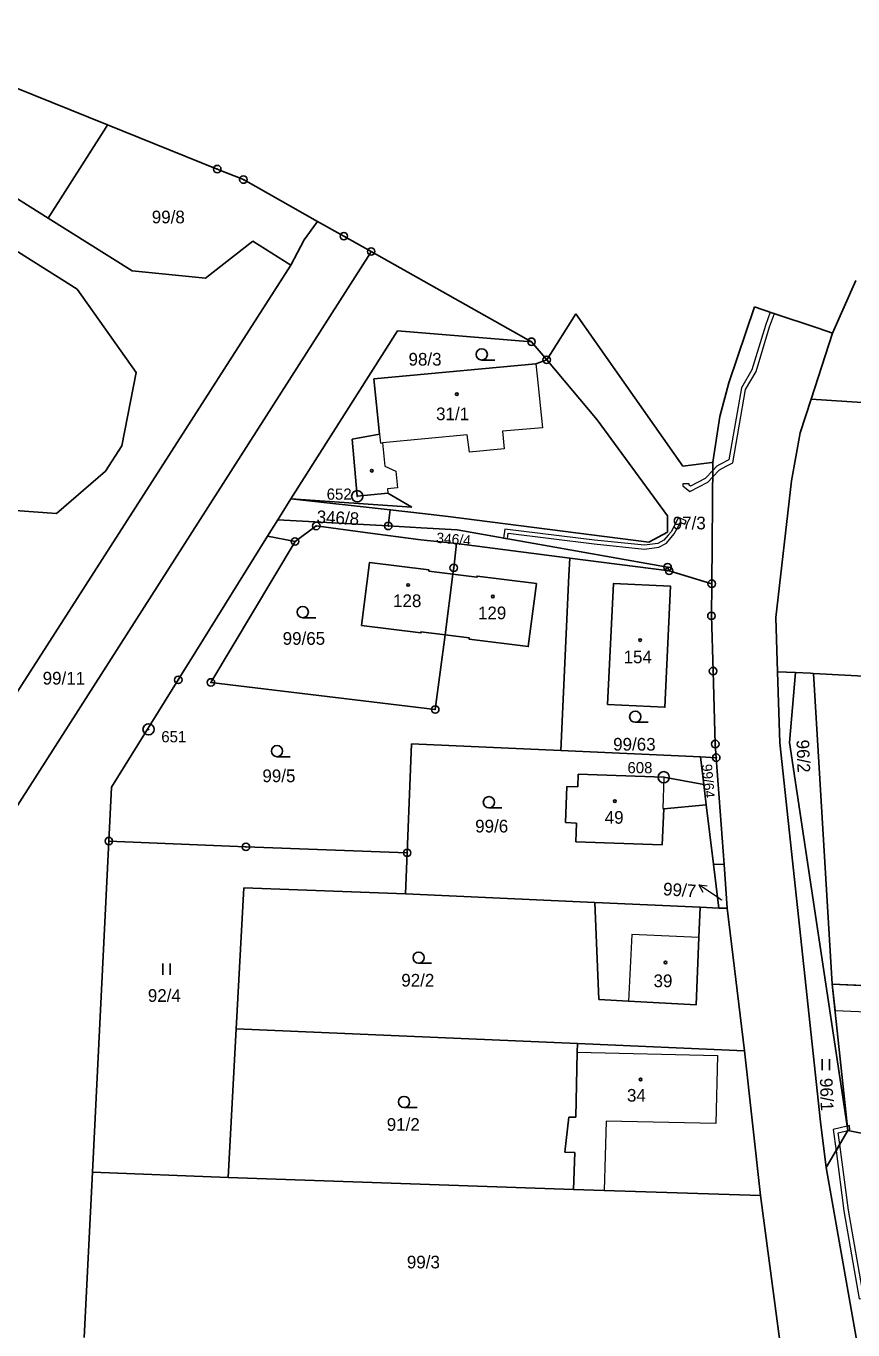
# Model space of a CAD drawing. Extents: x -645290 to -643454, y -1064771 to -1062356.
# Drawn here: x -644687.8 to -644577, y -1063528 to -1063353.2 of the extents above; entities that cross this region are included whole.
import ezdxf
from ezdxf.enums import TextEntityAlignment as Align

# ---------------------------------------------------------------- set-up
doc = ezdxf.new("R2010")
doc.units = 0
doc.header["$LTSCALE"] = 0.68
for name, color, linetype, lineweight in [('1', 7, 'Continuous', 25), ('13', 7, 'Continuous', 13), ('3', 7, 'Continuous', 25), ('4', 7, 'Continuous', 13), ('5', 7, 'Continuous', 25), ('7', 7, 'Continuous', 13), ('8', 7, 'Continuous', 25)]:
    doc.layers.add(name, color=color, linetype=linetype, lineweight=lineweight)
doc.layers.add('2', color=7, linetype='Continuous')

msp = doc.modelspace()

# ---------------------------------------------------------------- linework, layer by layer
at = {"layer": '1'}
for p, q in [((-644737.26, -1063353.21), (-644680.96, -1063388.46)), ((-644684.84, -1063378.96), (-644720.02, -1063356.92)), ((-644696.48, -1063358.55), (-644676.89, -1063366.45)), ((-644684.84, -1063378.96), (-644677.09, -1063366.77)), ((-644677.09, -1063366.77), (-644676.89, -1063366.45)), ((-644676.89, -1063366.45), (-644662.2, -1063372.38)), ((-644673.59, -1063386.01), (-644684.84, -1063378.96)), ((-644648.9, -1063379.59), (-644650.56, -1063381.87)), ((-644648.9, -1063379.59), (-644648.76, -1063379.39)), ((-644648.76, -1063379.39), (-644645.24, -1063381.37)), ((-644657.45, -1063382.05), (-644663.77, -1063387.01)), ((-644652.35, -1063385.28), (-644657.45, -1063382.05)), ((-644650.56, -1063381.87), (-644652.35, -1063385.28)), ((-644645.24, -1063381.37), (-644641.58, -1063383.43)), ((-644641.68, -1063383.59), (-644696.8, -1063469.92)), ((-644641.68, -1063383.59), (-644641.58, -1063383.43)), ((-644641.58, -1063383.43), (-644620.1, -1063395.53)), ((-644693.66, -1063449.74), (-644652.35, -1063385.28)), ((-644663.77, -1063387.01), (-644673.59, -1063386.01)), ((-644579.76, -1063394.36), (-644576.65, -1063387.33)), ((-644680.96, -1063388.46), (-644673.07, -1063399.66)), ((-644593.65, -1063401.05), (-644590.22, -1063390.86)), ((-644590.22, -1063390.86), (-644587.75, -1063391.69)), ((-644618.06, -1063397.95), (-644614.16, -1063391.77)), ((-644614.16, -1063391.77), (-644606.24, -1063403.04)), ((-644587.75, -1063391.69), (-644581.68, -1063393.72)), ((-644652.34, -1063416.6), (-644638.07, -1063394.05)), ((-644638.07, -1063394.05), (-644620.1, -1063395.53)), ((-644582.64, -1063403.23), (-644579.76, -1063394.36)), ((-644581.68, -1063393.72), (-644579.76, -1063394.36)), ((-644620.1, -1063395.53), (-644618.06, -1063397.95)), ((-644619.51, -1063398.51), (-644641.21, -1063400.48)), ((-644618.06, -1063397.95), (-644619.51, -1063398.51)), ((-644673.07, -1063399.66), (-644675, -1063409.48)), ((-644641.21, -1063400.48), (-644640.45, -1063407.93)), ((-644593.65, -1063401.05), (-644594.86, -1063405.54)), ((-644599.81, -1063412.19), (-644606.24, -1063403.04)), ((-644584.11, -1063407.75), (-644582.64, -1063403.23)), ((-644534.36, -1063406.42), (-644582.64, -1063403.23)), ((-644595.81, -1063411.69), (-644594.86, -1063405.54)), ((-644640.45, -1063407.93), (-644644.14, -1063408.59)), ((-644644.14, -1063408.59), (-644643.45, -1063416.24)), ((-644585.27, -1063414.18), (-644584.11, -1063407.75)), ((-644675, -1063409.48), (-644677.18, -1063412.9)), ((-644599.81, -1063412.19), (-644595.95, -1063411.71)), ((-644595.81, -1063411.69), (-644595.95, -1063427.97)), ((-644595.81, -1063411.69), (-644595.95, -1063411.71)), ((-644677.18, -1063412.9), (-644683.76, -1063418.54)), ((-644585.27, -1063414.18), (-644587.35, -1063432.48)), ((-644643.45, -1063416.24), (-644639.34, -1063415.83)), ((-644639.34, -1063415.83), (-644636.15, -1063417.71)), ((-644683.76, -1063418.54), (-644694.51, -1063417.77)), ((-644654.08, -1063419.4), (-644652.34, -1063416.6)), ((-644636.15, -1063417.71), (-644652.34, -1063416.6)), ((-644639.01, -1063418.08), (-644652.34, -1063416.6)), ((-644655.46, -1063421.61), (-644654.08, -1063419.4)), ((-644639.29, -1063420.22), (-644654.08, -1063419.4)), ((-644639.01, -1063418.08), (-644639.29, -1063420.22)), ((-644634.72, -1063418.55), (-644639.01, -1063418.08)), ((-644631.25, -1063418.96), (-644634.72, -1063418.55)), ((-644604.39, -1063422.39), (-644631.25, -1063418.96)), ((-644601.87, -1063418.87), (-644601.88, -1063421.06)), ((-644651.78, -1063422.31), (-644648.93, -1063420.23)), ((-644648.93, -1063420.23), (-644642.39, -1063421.09)), ((-644642.39, -1063421.09), (-644634.94, -1063422.08)), ((-644634.87, -1063420.47), (-644639.29, -1063420.22)), ((-644630.04, -1063420.74), (-644634.87, -1063420.47)), ((-644601.86, -1063425.75), (-644630.04, -1063420.74)), ((-644601.88, -1063421.06), (-644604.39, -1063422.39)), ((-644665.05, -1063437.05), (-644655.46, -1063421.61)), ((-644651.78, -1063422.31), (-644663.05, -1063441.2)), ((-644651.78, -1063422.31), (-644655.46, -1063421.61)), ((-644634.94, -1063422.08), (-644630.14, -1063422.56)), ((-644630.52, -1063425.84), (-644630.14, -1063422.56)), ((-644630.14, -1063422.56), (-644614.97, -1063424.54)), ((-644615.08, -1063426.87), (-644614.97, -1063424.54)), ((-644614.97, -1063424.54), (-644601.65, -1063426.24)), ((-644601.65, -1063426.24), (-644601.86, -1063425.75)), ((-644595.95, -1063427.97), (-644601.65, -1063426.24)), ((-644631.67, -1063434.83), (-644630.62, -1063426.69)), ((-644616.18, -1063450.33), (-644615.08, -1063426.87)), ((-644595.95, -1063427.97), (-644595.99, -1063432.28)), ((-644595.99, -1063432.28), (-644595.77, -1063439.68)), ((-644587.35, -1063432.48), (-644587.12, -1063439.78)), ((-644667.42, -1063440.86), (-644665.05, -1063437.05)), ((-644595.77, -1063439.68), (-644595.47, -1063449.46)), ((-644584.72, -1063439.88), (-644587.12, -1063439.78)), ((-644587.12, -1063439.78), (-644586.83, -1063449.3)), ((-644584.72, -1063439.88), (-644585.51, -1063449.26)), ((-644582.7, -1063439.97), (-644584.72, -1063439.88)), ((-644582.31, -1063439.99), (-644582.7, -1063439.97)), ((-644582.31, -1063439.99), (-644579.79, -1063481.67)), ((-644500.64, -1063444.4), (-644582.31, -1063439.99)), ((-644676.36, -1063455.23), (-644667.42, -1063440.86)), ((-644585.51, -1063449.26), (-644577.69, -1063501.25)), ((-644636.17, -1063449.42), (-644636.75, -1063464.05)), ((-644616.18, -1063450.33), (-644636.17, -1063449.42)), ((-644597.46, -1063451.19), (-644616.18, -1063450.33)), ((-644595.47, -1063449.46), (-644595.34, -1063451.29)), ((-644586.83, -1063449.3), (-644581.37, -1063500.1)), ((-644597.46, -1063451.19), (-644595.34, -1063451.29)), ((-644597.01, -1063454.88), (-644597.46, -1063451.19)), ((-644595.34, -1063451.29), (-644594.29, -1063465.62)), ((-644613.84, -1063453.49), (-644613.9, -1063455.19)), ((-644602.38, -1063453.91), (-644613.84, -1063453.49)), ((-644597.01, -1063454.88), (-644602.38, -1063453.91)), ((-644676.72, -1063462.47), (-644676.36, -1063455.23)), ((-644615.37, -1063455.14), (-644615.55, -1063460)), ((-644613.9, -1063455.19), (-644615.37, -1063455.14)), ((-644596.67, -1063457.63), (-644597.01, -1063454.88)), ((-644602.36, -1063458.13), (-644596.67, -1063457.63)), ((-644595.7, -1063465.56), (-644596.67, -1063457.63)), ((-644602.57, -1063462.99), (-644602.36, -1063458.13)), ((-644615.55, -1063460), (-644614.05, -1063460.05)), ((-644614.05, -1063460.05), (-644614.14, -1063462.56)), ((-644678.93, -1063506.84), (-644676.72, -1063462.47)), ((-644658.36, -1063463.25), (-644676.72, -1063462.47)), ((-644636.75, -1063464.05), (-644658.36, -1063463.25)), ((-644614.14, -1063462.56), (-644602.57, -1063462.99)), ((-644636.97, -1063469.54), (-644636.75, -1063464.05)), ((-644594.29, -1063465.62), (-644595.7, -1063465.56)), ((-644594.98, -1063471.46), (-644595.7, -1063465.56)), ((-644594.29, -1063465.62), (-644593.86, -1063471.46)), ((-644658.65, -1063468.72), (-644659.65, -1063487.63)), ((-644636.97, -1063469.54), (-644658.65, -1063468.72)), ((-644611.61, -1063470.7), (-644636.97, -1063469.54)), ((-644611.61, -1063470.7), (-644611.07, -1063483.72)), ((-644597.49, -1063471.35), (-644611.61, -1063470.7)), ((-644597.66, -1063475.39), (-644597.49, -1063471.35)), ((-644594.98, -1063471.46), (-644597.49, -1063471.35)), ((-644593.86, -1063471.46), (-644594.98, -1063471.46)), ((-644593.86, -1063471.46), (-644591.55, -1063490.59)), ((-644598.03, -1063484.42), (-644597.66, -1063475.39)), ((-644579.79, -1063481.67), (-644536.58, -1063483.49)), ((-644579.79, -1063481.67), (-644577.69, -1063501.25)), ((-644611.07, -1063483.72), (-644607.08, -1063483.93)), ((-644607.08, -1063483.93), (-644598.03, -1063484.42)), ((-644613.96, -1063490.75), (-644614.17, -1063499.5)), ((-644613.93, -1063489.61), (-644613.96, -1063490.75)), ((-644591.55, -1063490.59), (-644613.93, -1063489.61)), ((-644591.55, -1063490.59), (-644589.39, -1063509.99)), ((-644615.09, -1063499.48), (-644615.64, -1063504.18)), ((-644614.17, -1063499.5), (-644615.09, -1063499.48)), ((-644581.37, -1063500.1), (-644580.6, -1063506.24)), ((-644577.69, -1063501.25), (-644580.6, -1063506.24)), ((-644577.69, -1063501.25), (-644539.22, -1063509.16)), ((-644615.64, -1063504.18), (-644614.31, -1063504.23)), ((-644614.31, -1063504.23), (-644614.48, -1063509.16)), ((-644680.03, -1063529.01), (-644678.93, -1063506.84)), ((-644660.73, -1063507.57), (-644678.93, -1063506.84)), ((-644580.6, -1063506.24), (-644576.45, -1063529.78)), ((-644614.48, -1063509.16), (-644660.73, -1063507.57)), ((-644610.34, -1063509.3), (-644614.48, -1063509.16)), ((-644589.39, -1063509.99), (-644610.34, -1063509.3)), ((-644589.39, -1063509.99), (-644586.6, -1063531.21))]:
    msp.add_line(p, q, dxfattribs=at)
for points in [[(-644662.2, -1063372.38), (-644658.7, -1063373.79), (-644648.76, -1063379.39)], [(-644618.06, -1063397.95), (-644611.28, -1063406.01), (-644601.87, -1063418.87)], [(-644642.86, -1063433.55), (-644641.78, -1063425.11), (-644633.84, -1063426.12), (-644633.85, -1063426.27), (-644630.62, -1063426.69), (-644630.52, -1063425.84)], [(-644630.62, -1063426.69), (-644627.4, -1063427.1), (-644627.38, -1063426.95), (-644619.43, -1063427.96), (-644620.54, -1063436.4), (-644628.45, -1063435.39), (-644628.43, -1063435.24), (-644631.67, -1063434.83)], [(-644631.67, -1063434.83), (-644634.91, -1063434.42), (-644634.92, -1063434.56), (-644642.86, -1063433.55)], [(-644663.05, -1063441.2), (-644632.99, -1063444.83), (-644631.67, -1063434.83)], [(-644613.93, -1063489.61), (-644659.65, -1063487.63), (-644660.73, -1063507.57)]]:
    msp.add_lwpolyline(points, dxfattribs=at)
msp.add_lwpolyline([(-644609.91, -1063444.16), (-644602.23, -1063444.53), (-644601.46, -1063428.31), (-644609.1, -1063427.93)], close=True, dxfattribs=at)
at = {"layer": '13'}
for points in [[(-644598.87, -1063415.59), (-644596.45, -1063414.34), (-644595.83, -1063413.68), (-644594.9, -1063412.68), (-644594.03, -1063412.22), (-644593.13, -1063411.74), (-644591.4, -1063401.92), (-644590.01, -1063399.54), (-644588.19, -1063393.54), (-644587.54, -1063391.76), (-644587.75, -1063391.69), (-644588.11, -1063391.57), (-644588.76, -1063393.35), (-644590.57, -1063399.3), (-644591.98, -1063401.71), (-644593.67, -1063411.34), (-644594.85, -1063411.98), (-644595.27, -1063412.2), (-644595.82, -1063412.79), (-644596.81, -1063413.86), (-644598.81, -1063414.88), (-644598.95, -1063414.77), (-644598.96, -1063414.56), (-644599.84, -1063414.59), (-644599.83, -1063414.86)], [(-644623.85, -1063421.84), (-644623.33, -1063421.93), (-644623.21, -1063421.21), (-644611.7, -1063422.63), (-644604.96, -1063423.32), (-644603.02, -1063423.05), (-644602.01, -1063422.53), (-644601.59, -1063422.03), (-644600.98, -1063421.28), (-644600.14, -1063419.77), (-644599.57, -1063420), (-644599.38, -1063419.53), (-644600.42, -1063419.11), (-644601.4, -1063421), (-644601.77, -1063421.44), (-644602.35, -1063422.15), (-644603.16, -1063422.57), (-644604.95, -1063422.82), (-644611.64, -1063422.13), (-644623.65, -1063420.65)], [(-644536.58, -1063483.49), (-644579.79, -1063481.67), (-644579.41, -1063485.19), (-644536.15, -1063487.01)], [(-644579.29, -1063503.99), (-644578.8, -1063503.15), (-644579, -1063501.6), (-644577.69, -1063501.25), (-644577.75, -1063500.67), (-644577.78, -1063500.67), (-644579.66, -1063501.12)], [(-644577.75, -1063500.67), (-644577.69, -1063501.25), (-644577.44, -1063501.18), (-644577.48, -1063500.6)], [(-644578.8, -1063503.15), (-644579.29, -1063503.99), (-644578.24, -1063512.03), (-644576.17, -1063523.83), (-644575.34, -1063523.8), (-644572.63, -1063523.71), (-644572.59, -1063523.88), (-644573.02, -1063523.99), (-644572.93, -1063524.37), (-644572.5, -1063524.26), (-644572.2, -1063525.52), (-644573.09, -1063525.56), (-644573.07, -1063526.16), (-644571.44, -1063526.09), (-644572.16, -1063523.09), (-644575.39, -1063523.2), (-644575.67, -1063523.21), (-644577.64, -1063511.94)]]:
    msp.add_lwpolyline(points, close=True, dxfattribs=at)
at = {"layer": '3'}
for p, q in [((-644626.763, -1063397.98), (-644625.013, -1063397.98)), ((-644650.743, -1063432.53), (-644648.993, -1063432.53)), ((-644606.203, -1063446.55), (-644604.453, -1063446.55)), ((-644654.193, -1063451.16), (-644652.443, -1063451.16)), ((-644625.803, -1063458.01), (-644624.053, -1063458.01)), ((-644669.511, -1063480.4), (-644669.511, -1063478.9)), ((-644668.51, -1063480.4), (-644668.51, -1063478.9)), ((-644635.223, -1063478.85), (-644633.473, -1063478.85)), ((-644581.171, -1063493.19), (-644581.171, -1063491.69)), ((-644580.17, -1063493.19), (-644580.17, -1063491.69)), ((-644637.173, -1063498.19), (-644635.423, -1063498.19))]:
    msp.add_line(p, q, dxfattribs=at)
for centre in [(-644626.7629, -1063397.2298), (-644650.7429, -1063431.7798), (-644606.2029, -1063445.7998), (-644654.1929, -1063450.4098), (-644625.8029, -1063457.2598), (-644635.2229, -1063478.0998), (-644637.1729, -1063497.4398)]:
    msp.add_circle(centre, 0.75, dxfattribs=at)
at = {"layer": '4'}
for p, q in [((-644619.51, -1063398.51), (-644619.33, -1063400.15)), ((-644619.33, -1063400.15), (-644618.6, -1063407.06)), ((-644618.6, -1063407.06), (-644623.96, -1063407.52)), ((-644640.45, -1063407.93), (-644640.33, -1063409.12)), ((-644628.7, -1063407.99), (-644640.04, -1063409.1)), ((-644628.41, -1063410.33), (-644628.7, -1063407.99)), ((-644623.96, -1063407.52), (-644623.75, -1063409.89)), ((-644640.33, -1063409.12), (-644640.04, -1063409.1)), ((-644640.04, -1063409.1), (-644639.74, -1063412.21)), ((-644623.75, -1063409.89), (-644628.41, -1063410.33)), ((-644639.74, -1063412.21), (-644638.27, -1063412.88)), ((-644638.27, -1063412.88), (-644638.04, -1063415.11)), ((-644638.04, -1063415.11), (-644639.39, -1063415.25)), ((-644639.39, -1063415.25), (-644639.34, -1063415.83)), ((-644602.38, -1063453.91), (-644602.51, -1063458.12)), ((-644602.51, -1063458.12), (-644602.36, -1063458.13)), ((-644606.64, -1063474.98), (-644607.08, -1063483.93)), ((-644597.66, -1063475.39), (-644606.64, -1063474.98)), ((-644613.96, -1063490.75), (-644595.16, -1063491.21)), ((-644595.16, -1063491.21), (-644595.39, -1063500.33)), ((-644610.11, -1063500.01), (-644610.34, -1063509.3)), ((-644595.39, -1063500.33), (-644610.11, -1063500.01))]:
    msp.add_line(p, q, dxfattribs=at)
at = {"layer": '5'}
for centre in [(-644630.1068, -1063402.5492), (-644641.4968, -1063412.8192), (-644636.6268, -1063428.1392), (-644625.2668, -1063429.6792), (-644605.5468, -1063435.5192), (-644608.9268, -1063457.1192), (-644602.1368, -1063478.7492), (-644605.4768, -1063494.4292)]:
    msp.add_circle(centre, 0.175, dxfattribs=at)
at = {"layer": '7'}
msp.add_line((-644597.678, -1063468.322), (-644597.128, -1063469.297), dxfattribs=at)
msp.add_lwpolyline([(-644594.65, -1063470.37), (-644595.19, -1063470), (-644597.678, -1063468.322), (-644596.568, -1063468.467)], dxfattribs=at)
at = {"layer": '8'}
for centre, radius in [((-644662.2, -1063372.3799), 0.5), ((-644662.2, -1063372.3799), 0.0303), ((-644658.7, -1063373.7899), 0.5), ((-644658.7, -1063373.7899), 0.0303), ((-644645.24, -1063381.3699), 0.5), ((-644645.24, -1063381.3699), 0.0303), ((-644641.58, -1063383.4299), 0.5), ((-644641.58, -1063383.4299), 0.0303), ((-644620.1, -1063395.5299), 0.5), ((-644620.1, -1063395.5299), 0.0303), ((-644618.06, -1063397.9499), 0.5), ((-644618.06, -1063397.9499), 0.0303), ((-644643.45, -1063416.2398), 0.75), ((-644643.45, -1063416.2398), 0.03), ((-644648.93, -1063420.2299), 0.5), ((-644648.93, -1063420.2299), 0.0303), ((-644639.29, -1063420.2199), 0.5), ((-644639.29, -1063420.2199), 0.0303), ((-644651.78, -1063422.3099), 0.5), ((-644651.78, -1063422.3099), 0.0303), ((-644630.52, -1063425.8399), 0.5), ((-644630.52, -1063425.8399), 0.0303), ((-644601.86, -1063425.7499), 0.5), ((-644601.65, -1063426.2399), 0.5), ((-644601.86, -1063425.7499), 0.0303), ((-644601.65, -1063426.2399), 0.0303), ((-644595.95, -1063427.9699), 0.5), ((-644595.95, -1063427.9699), 0.0303), ((-644595.99, -1063432.2799), 0.5), ((-644595.99, -1063432.2799), 0.0303), ((-644667.42, -1063440.8599), 0.5), ((-644595.77, -1063439.6799), 0.5), ((-644595.77, -1063439.6799), 0.0303), ((-644667.42, -1063440.8599), 0.0303), ((-644663.05, -1063441.1999), 0.5), ((-644663.05, -1063441.1999), 0.0303), ((-644632.99, -1063444.8299), 0.5), ((-644632.99, -1063444.8299), 0.0303), ((-644671.41, -1063447.4898), 0.75), ((-644671.41, -1063447.4898), 0.03), ((-644595.47, -1063449.4599), 0.5), ((-644595.34, -1063451.2899), 0.5), ((-644595.47, -1063449.4599), 0.0303), ((-644595.34, -1063451.2899), 0.0303), ((-644602.38, -1063453.9098), 0.75), ((-644602.38, -1063453.9098), 0.03), ((-644676.72, -1063462.4699), 0.5), ((-644676.72, -1063462.4699), 0.0303), ((-644658.36, -1063463.2499), 0.5), ((-644658.36, -1063463.2499), 0.0303), ((-644636.75, -1063464.0499), 0.5), ((-644636.75, -1063464.0499), 0.0303)]:
    msp.add_circle(centre, radius, dxfattribs=at)

# ---------------------------------------------------------------- texts
at = {"layer": '2'}
for s, height, p in [('99/8', 1.7, (-644668.759, -1063379.655)), ('98/3', 1.7, (-644634.359, -1063398.725)), ('31/1', 1.7, (-644630.669, -1063406.045)), ('97/3', 1.7, (-644598.959, -1063420.685)), ('128', 1.7, (-644636.749, -1063431.104)), ('129', 1.7, (-644625.369, -1063432.735)), ('99/65', 1.7, (-644650.59, -1063436.155)), ('154', 1.7, (-644605.859, -1063438.635)), ('99/11', 1.7, (-644682.75, -1063441.485)), ('99/63', 1.7, (-644606.31, -1063450.344)), ('99/5', 1.7, (-644653.939, -1063454.574)), ('99/6', 1.7, (-644625.429, -1063461.314)), ('49', 1.7, (-644609.019, -1063460.145)), ('99/7', 0.2, (-644594.649, -1063470.42)), ('92/2', 1.7, (-644635.329, -1063481.975)), ('39', 1.7, (-644602.479, -1063482.054)), ('34', 1.7, (-644606.039, -1063497.405)), ('91/2', 1.7, (-644637.279, -1063501.314)), ('99/3', 1.7, (-644634.579, -1063519.755))]:
    msp.add_text(s, height=height, dxfattribs=at).set_placement(p, align=Align.CENTER)
for s, height, rotation, p in [('346/8', 1.7, 357, (-644646.0795, -1063419.9746)), ('346/4', 1.386, 355, (-644630.5884, -1063422.6773)), ('99/64', 1.361, 275, (-644597.0855, -1063454.4692))]:
    msp.add_text(s, height=height, rotation=rotation, dxfattribs=at).set_placement(p, align=Align.CENTER)
for s, p in [('96/2', (-644584.594, -1063448.904)), ('96/1', (-644581.464, -1063494.264))]:
    msp.add_text(s, height=1.7, rotation=272, dxfattribs=at).set_placement(p)
msp.add_text('99/7', height=1.7, rotation=356, dxfattribs=at).set_placement((-644598.0996, -1063470.0279), align=Align.RIGHT)
msp.add_text('92/4', height=1.7, dxfattribs=at).set_placement((-644671.5, -1063484.025))
at = {"layer": '8'}
for s, p in [('652', (-644647.54, -1063416.705)), ('651', (-644669.7, -1063449.225))]:
    msp.add_text(s, height=1.5, dxfattribs=at).set_placement(p)
msp.add_text('608', height=1.5, dxfattribs=at).set_placement((-644603.889, -1063453.377), align=Align.RIGHT)

doc.saveas('drawing.dxf')
